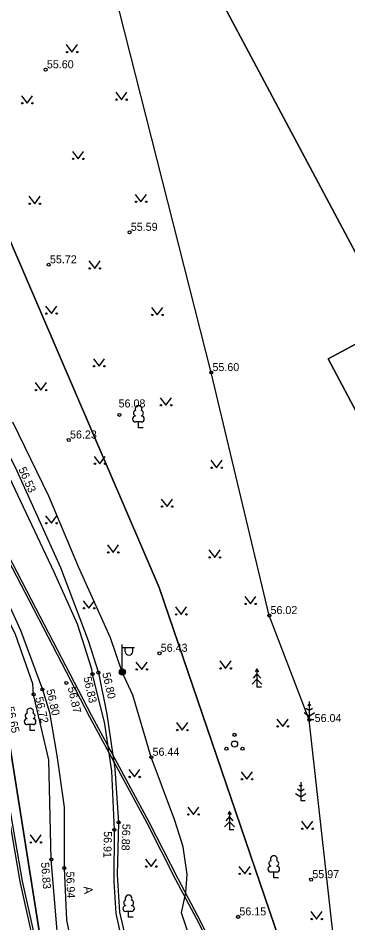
# Model space of a CAD drawing. Extents: x 542320 to 543602, y 6558748 to 6559969.
# Drawn here: x 542621.2 to 542647.9, y 6559275.6 to 6559349.1 of the extents above; entities that cross this region are included whole.
import ezdxf

# ---------------------------------------------------------------- set-up
doc = ezdxf.new("R2010")
doc.units = 0
for name, color, linetype in [('HALJASTUS', 7, 'Continuous'), ('KORGUS-EH2000', 7, 'Continuous'), ('KPKAABEL', 7, 'Continuous'), ('mootpiir', 7, 'Continuous'), ('MPKAABEL', 7, 'Continuous'), ('PIIR', 7, 'Continuous'), ('POST', 7, 'Continuous'), ('PUU', 7, 'Continuous'), ('TEE', 7, 'Continuous')]:
    doc.layers.add(name, color=color, linetype=linetype)

# ---------------------------------------------------------------- blocks, each defined once
blk = doc.blocks.new('LEHTP1')
for p, q in [((0.48, 0.95), (-0.48, 0.95)), ((0, 0), (0, 0.95)), ((0.76, 0), (0, 0))]:
    blk.add_line(p, q)
for centre, radius, start, end in [((0, 3.04), 0.554, 332.5799, 207.4201), ((-0.47, 1.42), 0.475, 90.0016, 269.3953), ((-0.34, 2.35), 0.465, 109.0217, 253.1415), ((0.34, 2.35), 0.465, 286.8508, 70.9859), ((0.47, 1.42), 0.475, 270.6047, 89.9984)]:
    blk.add_arc(centre, radius, start, end)
blk = doc.blocks.new('KUUSK1')
for p, q in [((0, 3), (-0.3, 2.5)), ((0.3, 2.5), (0, 3)), ((0, 3), (0, 0)), ((0, 2.2), (-0.6, 1.5)), ((0.6, 1.5), (0, 2.2)), ((0, 1.3), (-0.8, 0.5)), ((0.8, 0.5), (0, 1.3)), ((0.72, 0), (0, 0))]:
    blk.add_line(p, q)
blk = doc.blocks.new('MAND1')
for p, q in [((0, 3), (0, 0)), ((0, 1.5), (-0.53, 1.86)), ((0, 2.3), (-0.25, 2.47)), ((0.25, 2.47), (0, 2.3)), ((0.53, 1.86), (0, 1.5)), ((-0.85, 1.18), (0, 0.61)), ((0, 0.61), (0.85, 1.18)), ((0.72, 0), (0, 0))]:
    blk.add_line(p, q)
blk = doc.blocks.new('PQQSAS')
for centre, radius in [((0, 1.5), 0.25), ((0, 0), 0.5), ((-1.3, -0.75), 0.25), ((1.3, -0.75), 0.25)]:
    blk.add_circle(centre, radius)
blk = doc.blocks.new('MEPOST')
for radius in [0.5, 0.45, 0.4, 0.35, 0.3, 0.25, 0.2, 0.15, 0.1, 0.05]:
    blk.add_circle((0, 0), radius)
blk = doc.blocks.new('VAPOST')
for p, q in [((0, 0.5), (0, 4.5)), ((0, 4), (2, 4)), ((0.45, 3.36), (0.45, 4)), ((1.68, 3.36), (1.68, 4))]:
    blk.add_line(p, q)
blk.add_arc((1.07, 3.36), 0.613, 180, 0)
blk = doc.blocks.new('MURU')
for p, q in [((-0.93, 1.21), (0, 0)), ((0, 0), (0.89, 1.21))]:
    blk.add_line(p, q)
for centre in [(-0.8, 0), (0.86, 0)]:
    blk.add_circle(centre, 0.11)
blk = doc.blocks.new('RING02')
blk.add_circle((0, 0), 0.25)

msp = doc.modelspace()

# ---------------------------------------------------------------- linework, layer by layer
at = {"layer": 'KPKAABEL'}
for points in [[(542592.521, 6559362.446), (542597.547, 6559351.945), (542600.14, 6559344.366), (542606.118, 6559332.403), (542610.857, 6559323.162), (542616.273, 6559312.944), (542622.065, 6559301.812), (542626.969, 6559292.384), (542631.614, 6559283.754), (542633.958, 6559279.16), (542635.835, 6559275.606), (542642.325, 6559262.55)], [(542592.701, 6559362.532), (542597.732, 6559352.021), (542600.325, 6559344.443), (542606.296, 6559332.493), (542611.034, 6559323.254), (542616.45, 6559313.037), (542622.242, 6559301.904), (542627.146, 6559292.478), (542631.791, 6559283.847), (542634.136, 6559279.252), (542636.013, 6559275.697), (542642.504, 6559262.639)], [(542629.705, 6559255.548), (542624.459, 6559265.014), (542621.333, 6559278.998), (542619.565, 6559289.352), (542615.605, 6559299.115), (542610.376, 6559310.033), (542605.393, 6559319.873), (542600.368, 6559330.022), (542596.984, 6559338.198), (542596.381, 6559342.121), (542596.809, 6559346.972), (542595.758, 6559350.645), (542591.144, 6559359.29), (542590.252, 6559360.802)], [(542629.88, 6559255.645), (542624.648, 6559265.086), (542621.529, 6559279.037), (542619.758, 6559289.407), (542615.788, 6559299.196), (542610.555, 6559310.121), (542605.572, 6559319.963), (542600.55, 6559330.105), (542597.178, 6559338.252), (542596.582, 6559342.128), (542597.011, 6559346.991), (542595.944, 6559350.72), (542591.318, 6559359.388), (542590.424, 6559360.904)]]:
    msp.add_lwpolyline(points, dxfattribs=at)
at = {"layer": 'mootpiir'}
msp.add_lwpolyline([(542580.596, 6559350.501), (542576.13, 6559347.213), (542573.572, 6559344.253), (542570.527, 6559343.48), (542613.7, 6559249.972), (542615.953, 6559250.584), (542618.546, 6559251.554), (542622.286, 6559253.49), (542626.884, 6559255.347), (542629.88, 6559255.645), (542630.445, 6559256.8), (542630.818, 6559257.341), (542632.786, 6559258.084), (542634.681, 6559258.868), (542635.466, 6559259.163), (542639.905, 6559261.019), (542642.325, 6559262.55), (542647.794, 6559265.185), (542644.803, 6559292.129), (542641.558, 6559300.605), (542636.848, 6559320.338), (542627.616, 6559356.728)], dxfattribs=at)
at = {"layer": 'MPKAABEL'}
msp.add_lwpolyline([(542635.764, 6559272.462), (542634.442, 6559276.457), (542634.798, 6559278.099), (542634.887, 6559279.567), (542634.569, 6559281.81), (542633.888, 6559283.965), (542631.986, 6559289.097), (542630.487, 6559294.149), (542629.634, 6559296.011), (542628.667, 6559298.791), (542626.087, 6559304.547), (542623.663, 6559310.291), (542620.741, 6559316.319)], dxfattribs=at)
at = {"layer": 'PIIR'}
for points in [[(542456.68, 6559581.07), (542523.83, 6559477.46), (542537.52, 6559453.62), (542591.81, 6559358.92), (542597.79, 6559348.5), (542599.76, 6559343.89), (542619.08, 6559298.96), (542624.28, 6559266.08), (542637.46, 6559233.17), (542680, 6559143.81), (542700.43, 6559093.84), (542700.92, 6559090.29), (542704.02, 6559067.82)], [(542632.02, 6559361.13), (542641.94, 6559366.51), (542667.3, 6559379.98), (542686.87, 6559343.19), (542661.3, 6559329.57), (542651.63, 6559324.28), (542632.02, 6559361.13)], [(542632.63, 6559302.87), (542612.16, 6559350.51), (542632.02, 6559361.13), (542651.63, 6559324.28), (542646.33, 6559321.44), (542665.85, 6559284.72), (542671.39, 6559287.65), (542689.34, 6559253.48), (542704.9, 6559215.47), (542674.63, 6559203.23), (542672.45, 6559208.6), (542665.71, 6559205.86), (542632.63, 6559302.87)], [(542612.16, 6559350.51), (542632.63, 6559302.87), (542665.71, 6559205.86), (542667.87, 6559200.49), (542682.31, 6559164.31), (542683.94, 6559160.9), (542699.54, 6559124.27), (542718.47, 6559078.4), (542700.92, 6559090.29), (542700.43, 6559093.84), (542680, 6559143.81), (542637.46, 6559233.17), (542624.28, 6559266.08), (542619.08, 6559298.96), (542599.76, 6559343.89), (542612.16, 6559350.51)], [(542665.85, 6559284.72), (542646.33, 6559321.44), (542651.63, 6559324.28), (542661.3, 6559329.57), (542686.87, 6559343.19), (542706.55, 6559306.41), (542671.39, 6559287.65), (542665.85, 6559284.72)]]:
    msp.add_lwpolyline(points, dxfattribs=at)
at = {"layer": 'TEE'}
for points in [[(542624.102, 6559367.101), (542623.091, 6559366.625), (542619.655, 6559364.738), (542606.495, 6559357.531), (542598.927, 6559352.716), (542596.394, 6559351.262), (542597.483, 6559348.273), (542599.096, 6559344.51), (542601.523, 6559338.799), (542604.022, 6559333.449), (542609.839, 6559322.477), (542616.479, 6559310.106), (542621.369, 6559299.405), (542623.152, 6559294.601), (542623.728, 6559292.736), (542624.325, 6559289.249), (542624.923, 6559285.031), (542624.921, 6559280.093), (542625.11, 6559275.875), (542626.159, 6559270.713), (542630.818, 6559257.341)], [(542634.681, 6559258.868), (542630.146, 6559271.916), (542629.129, 6559276.409), (542628.98, 6559278.994), (542628.987, 6559283.205), (542628.787, 6559287.956), (542628.207, 6559291.798), (542627.216, 6559295.847), (542627.153, 6559296.256), (542626, 6559299.915), (542624.094, 6559304.138), (542620.263, 6559312.262), (542613.869, 6559324.503), (542608.179, 6559335.156), (542606.426, 6559338.985), (542605.717, 6559341.19), (542605.399, 6559342.931), (542605.274, 6559345.104), (542605.472, 6559347.122), (542606.079, 6559349.35), (542607.837, 6559352.387), (542608.749, 6559353.701), (542625.256, 6559362.999)], [(542625.586, 6559362.35), (542608.76, 6559352.379), (542607.276, 6559350.302), (542606.168, 6559347.789), (542605.934, 6559345.297), (542606.434, 6559342.484), (542606.994, 6559340.503), (542609.201, 6559335.669), (542614.601, 6559324.827), (542620.939, 6559312.64), (542624.605, 6559304.516), (542626.856, 6559298.567), (542627.692, 6559295.961), (542628.381, 6559292.605), (542629.031, 6559288.15), (542629.33, 6559283.803), (542629.221, 6559279.539), (542629.398, 6559276.511), (542629.819, 6559274.787), (542630.575, 6559272.193), (542635.466, 6559259.163)], [(542630.445, 6559256.8), (542625.172, 6559270.111), (542624.375, 6559274.673), (542623.873, 6559280.787), (542623.665, 6559288.876), (542622.433, 6559294.202), (542622.365, 6559295.059), (542620.97, 6559299.05), (542615.719, 6559309.698), (542609.023, 6559322.07), (542603.292, 6559332.961), (542601.008, 6559337.652), (542600.271, 6559338.024), (542599.29, 6559338.496), (542598.116, 6559339.729), (542596.153, 6559343.676), (542594.87, 6559346.799)]]:
    msp.add_lwpolyline(points, dxfattribs=at)

# ---------------------------------------------------------------- block references
at = {"layer": 'HALJASTUS', "xscale": 0.5, "yscale": 0.5}
for p in [(542625.545, 6559346.366), (542629.563, 6559342.498), (542621.909, 6559342.205), (542626.044, 6559337.691), (542622.522, 6559334.044), (542631.146, 6559334.204), (542627.395, 6559328.794), (542623.876, 6559325.13), (542632.468, 6559325.013), (542627.747, 6559320.852), (542623.025, 6559318.918), (542633.173, 6559317.675), (542627.806, 6559312.927), (542637.278, 6559312.605), (542633.26, 6559309.455), (542623.874, 6559308.092), (542628.891, 6559305.733), (542637.131, 6559305.323), (542640.034, 6559301.543), (542626.926, 6559301.191), (542634.404, 6559300.693), (542631.209, 6559296.223), (542638.012, 6559296.311), (542634.493, 6559291.3), (542642.646, 6559291.593), (542630.622, 6559287.49), (542639.742, 6559287.302), (542635.402, 6559284.443), (542644.639, 6559283.288), (542622.611, 6559282.178), (542631.971, 6559280.21), (542639.566, 6559279.624), (542645.401, 6559275.951)]:
    msp.add_blockref('MURU', p, dxfattribs=at)
at = {"layer": 'KORGUS-EH2000', "xscale": 0.5, "yscale": 0.5}
for p in [(542623.411, 6559344.929), (542630.222, 6559331.731), (542623.66, 6559329.089), (542636.848, 6559320.338), (542629.4, 6559316.899), (542625.29, 6559314.863), (542641.558, 6559300.605), (542632.651, 6559297.54), (542627.692, 6559295.961), (542625.084, 6559295.134), (542627.216, 6559295.847), (542623.152, 6559294.601), (542622.433, 6559294.202), (542644.803, 6559292.129), (542631.986, 6559289.097), (542629.33, 6559283.803), (542628.987, 6559283.205), (542623.873, 6559280.787), (542624.921, 6559280.093), (542644.953, 6559279.158), (542639.032, 6559276.132)]:
    msp.add_blockref('RING02', p, dxfattribs=at)
at = {"layer": 'POST', "xscale": 0.5, "yscale": 0.5}
for name in ['VAPOST', 'MEPOST']:
    msp.add_blockref(name, (542629.634, 6559296.011), dxfattribs=at)
at = {"layer": 'PUU', "xscale": 0.5, "yscale": 0.5}
for name, p in [('LEHTP1', (542630.94, 6559315.855)), ('KUUSK1', (542640.561, 6559294.773)), ('LEHTP1', (542622.155, 6559291.273)), ('MAND1', (542644.803, 6559292.129)), ('PQQSAS', (542638.739, 6559290.163)), ('MAND1', (542644.112, 6559285.563)), ('KUUSK1', (542638.336, 6559283.186)), ('LEHTP1', (542641.927, 6559279.299)), ('LEHTP1', (542630.146, 6559276.102))]:
    msp.add_blockref(name, p, dxfattribs=at)

# ---------------------------------------------------------------- texts
at = {"layer": 'KORGUS-EH2000'}
for s, p in [('55.60', (542623.511, 6559345.046)), ('55.59', (542630.322, 6559331.848)), ('55.72', (542623.76, 6559329.206)), ('55.60', (542636.948, 6559320.455)), ('56.08', (542629.333, 6559317.503)), ('56.23', (542625.39, 6559314.98)), ('56.02', (542641.658, 6559300.722)), ('56.43', (542632.751, 6559297.657)), ('56.04', (542645.238, 6559291.95)), ('56.44', (542632.086, 6559289.214)), ('55.97', (542645.053, 6559279.275)), ('56.15', (542639.132, 6559276.249))]:
    msp.add_text(s, height=0.65, dxfattribs=at).set_placement(p)
for s, rotation, p in [('56.53', 294.24689, (542621.186, 6559312.488)), ('56.80', 282.85074, (542628.003, 6559295.909)), ('56.83', 282.85074, (542626.473, 6559295.568)), ('56.80', 282.85074, (542623.463, 6559294.549)), ('56.87', 282.85074, (542625.197, 6559294.743)), ('56.72', 282.85074, (542622.553, 6559293.916)), ('56.65', 282.85074, (542620.197, 6559293.13)), ('56.88', 267.87683, (542629.647, 6559283.695)), ('56.91', 268.86205, (542628.141, 6559283.095)), ('56.83', 274.57873, (542623.036, 6559280.543)), ('56.94', 272.04745, (542625.076, 6559279.8))]:
    msp.add_text(s, height=0.65, rotation=rotation, dxfattribs=at).set_placement(p)
at = {"layer": 'TEE'}
msp.add_text('A', height=0.7, rotation=276.43496, dxfattribs=at).set_placement((542626.493, 6559278.582))

doc.saveas('drawing.dxf')
